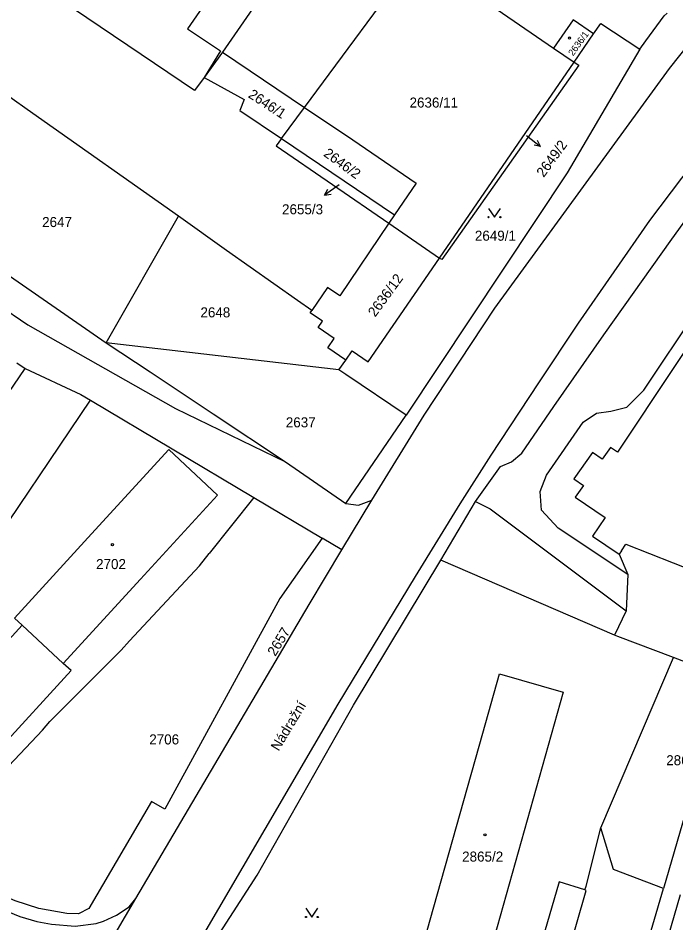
# Model space of a CAD drawing. Extents: x -527335 to -526256, y -1079142 to -1077809.
# Drawn here: x -527132.2 to -527020.7, y -1078877.1 to -1078723.7 of the extents above; entities that cross this region are included whole.
import ezdxf

# ---------------------------------------------------------------- set-up
doc = ezdxf.new("R2010")
doc.units = 0
for name, color, linetype in [('Vrstva 1', 7, 'Continuous'), ('Vrstva 2', 7, 'Continuous'), ('Vrstva 3', 7, 'Continuous'), ('Vrstva 4', 7, 'Continuous'), ('Vrstva 5', 7, 'Continuous'), ('Vrstva 7', 7, 'Continuous')]:
    doc.layers.add(name, color=color, linetype=linetype)

msp = doc.modelspace()

# ---------------------------------------------------------------- linework, layer by layer
at = {"layer": 'Vrstva 1'}
for p, q in [((-527097.53, -1078729.48), (-527100.64, -1078733.75)), ((-527097.53, -1078729.48), (-527083.63, -1078738.83)), ((-527060.76, -1078764.37), (-527037.96, -1078731.19)), ((-527087.53, -1078744.11), (-527083.63, -1078738.83)), ((-527087.53, -1078744.11), (-527068.38, -1078757.06)), ((-527117.23, -1078778.72), (-527104.99, -1078757.3)), ((-527068.38, -1078757.06), (-527069.34, -1078758.47)), ((-527148.09, -1078757.41), (-527117.23, -1078778.72)), ((-527069.34, -1078758.47), (-527060.76, -1078764.37)), ((-527077.82, -1078783.31), (-527117.23, -1078778.72)), ((-527077.82, -1078783.31), (-527076.65, -1078781.68)), ((-527076.62, -1078805.97), (-527066.43, -1078791.03)), ((-527077.3, -1078813.84), (-527072.22, -1078805.43)), ((-527077.3, -1078813.84), (-527080.64, -1078811.86)), ((-527031.1, -1078828.29), (-527060.55, -1078815.59)), ((-527131.44, -1078826.61), (-527124.5, -1078833.07)), ((-527033.44, -1078860.94), (-527021.11, -1078832.09)), ((-526983.93, -1078846.24), (-527021.11, -1078832.09))]:
    msp.add_line(p, q, dxfattribs=at)
for points in [[(-527072.22, -1078805.43), (-527063.35, -1078791.03), (-527051.39, -1078772.86), (-527021.8, -1078732.24), (-527016.31, -1078725.38), (-526999.22, -1078705.77), (-526979.26, -1078684.5), (-526961.36, -1078666.17), (-526945.34, -1078649.61), (-526932.24, -1078641.62), (-526929.63, -1078639.61), (-526929.14, -1078637.23), (-526930.46, -1078635.68), (-526927.65, -1078633), (-526895.17, -1078602.34)], [(-527100.64, -1078733.75), (-527102.25, -1078735.96), (-527127.31, -1078719.02), (-527111.05, -1078694.45)], [(-527080.84, -1078705.04), (-527083.41, -1078706.65), (-527085.52, -1078706.27), (-527089.43, -1078704.54), (-527090.21, -1078705.74), (-527091.13, -1078707.66), (-527103.45, -1078725.55), (-527097.86, -1078729.26), (-527100.64, -1078733.75)], [(-527080.84, -1078705.04), (-527085.2, -1078711.65), (-527097.53, -1078729.48)], [(-527083.63, -1078738.83), (-527064.48, -1078712.94), (-527041.46, -1078728.79), (-527037.96, -1078731.19)], [(-527026.84, -1078728.96), (-527025.8, -1078727.55), (-527022.69, -1078723.31), (-527022.2, -1078722.85)], [(-526998.63, -1078724.92), (-527007.36, -1078735.07), (-527019.76, -1078750.86), (-527025.21, -1078757.99), (-527037.26, -1078775.41), (-527043.97, -1078785.5), (-527052.05, -1078797.8), (-527057.33, -1078806.06), (-527064.89, -1078818.36), (-527077.97, -1078839.97), (-527106.45, -1078888.73), (-527179.38, -1079013.92), (-527179.74, -1079015.3)], [(-527060.55, -1078815.59), (-527054.66, -1078805.64), (-527050.43, -1078799.71), (-527048.56, -1078798.89), (-527046.8, -1078797.42), (-527041.37, -1078789.55), (-527032.93, -1078777.37), (-527021.38, -1078761.15), (-527014.2, -1078751.18), (-527004.39, -1078737.66), (-526998.1, -1078729.59), (-526996.78, -1078727.49), (-526996.17, -1078726.12), (-526997.1, -1078724.79), (-526998.63, -1078724.92)], [(-527037.96, -1078731.19), (-527034.65, -1078726.37), (-527033.45, -1078724.63), (-527026.84, -1078728.96)], [(-527026.84, -1078728.96), (-527039.13, -1078749.94), (-527066.43, -1078791.03)], [(-527037.96, -1078731.19), (-527037.19, -1078731.69), (-527060.38, -1078764.63), (-527060.76, -1078764.37)], [(-527100.64, -1078733.75), (-527093.86, -1078737.51), (-527094.58, -1078739.34), (-527087.53, -1078744.11)], [(-527104.99, -1078757.3), (-527129.66, -1078739.88), (-527134.11, -1078736.73), (-527148.09, -1078757.41)], [(-527083.63, -1078738.83), (-527075.44, -1078744.34), (-527064.73, -1078751.68), (-527068.38, -1078757.06)], [(-527087.53, -1078744.11), (-527088.44, -1078745.34), (-527069.34, -1078758.47)], [(-527082.38, -1078773.28), (-527084.82, -1078771.55), (-527096.82, -1078763.08), (-527104.99, -1078757.3)], [(-527069.34, -1078758.47), (-527077.66, -1078770.78), (-527079.76, -1078769.36), (-527082.38, -1078773.28)], [(-527076.65, -1078781.68), (-527075.57, -1078780.1), (-527072.85, -1078781.96), (-527060.76, -1078764.37)], [(-527003.07, -1078773.49), (-527011.16, -1078768.09), (-527030.63, -1078797.3), (-527031.8, -1078796.49), (-527033.21, -1078798.48), (-527034.85, -1078797.32), (-527038.02, -1078801.77), (-527036.37, -1078802.94), (-527037.76, -1078804.91), (-527032.72, -1078808.35), (-527034.82, -1078811.52), (-527030.31, -1078814.54), (-527028.85, -1078818), (-527029.14, -1078824.18), (-527031.1, -1078828.29)], [(-527076.65, -1078781.68), (-527079.71, -1078779.62), (-527078.61, -1078778.01), (-527081.31, -1078776.16), (-527080.58, -1078775.08), (-527082.65, -1078773.68), (-527082.38, -1078773.28)], [(-527117.23, -1078778.72), (-527109.79, -1078783.67), (-527099.09, -1078790.78), (-527086.87, -1078798.91), (-527076.62, -1078805.97)], [(-527132.36, -1078782.16), (-527130.96, -1078783.09), (-527121.51, -1078787.51), (-527119.86, -1078788.49)], [(-527066.43, -1078791.03), (-527076.61, -1078784.13), (-527077.82, -1078783.31)], [(-527172.24, -1078856.19), (-527141.71, -1078814.86), (-527138.98, -1078816.71), (-527119.86, -1078788.49)], [(-527119.86, -1078788.49), (-527092.2, -1078804.98), (-527080.64, -1078811.86)], [(-527124.5, -1078833.07), (-527111.43, -1078818.8), (-527098.36, -1078804.54), (-527106.61, -1078796.85), (-527119.69, -1078811.12), (-527132.76, -1078825.39), (-527131.44, -1078826.61)], [(-527076.62, -1078805.97), (-527074.47, -1078806.26), (-527072.22, -1078805.43)], [(-527080.64, -1078811.86), (-527087.81, -1078822.05), (-527107.3, -1078857.78), (-527109.58, -1078856.49), (-527120.15, -1078874.63), (-527121.91, -1078875.54), (-527123.9, -1078875.45), (-527128.65, -1078874.62), (-527132.64, -1078873.34), (-527143.8, -1078868.59), (-527146.2, -1078867.57), (-527172.24, -1078856.19)], [(-527112.22, -1078872.94), (-527082.87, -1078823.07), (-527077.3, -1078813.84)], [(-527106.29, -1078891.74), (-527106.04, -1078891.29), (-527091.65, -1078868.97), (-527075.33, -1078840.18), (-527060.55, -1078815.59)], [(-527131.44, -1078826.61), (-527144.07, -1078840.4), (-527144.58, -1078840.95), (-527157.72, -1078855.29), (-527149.33, -1078862.84), (-527144.03, -1078857.05), (-527136.25, -1078848.56), (-527135.69, -1078847.95), (-527123.17, -1078834.29), (-527124.5, -1078833.07)], [(-527021.11, -1078832.09), (-527030.54, -1078828.5), (-527031.1, -1078828.29)], [(-527221.67, -1078833.78), (-527221.62, -1078835.3), (-527221.22, -1078836.2), (-527220.43, -1078836.77), (-527209.47, -1078841.8), (-527166.12, -1078861.35), (-527149.23, -1078868.84), (-527131.87, -1078875.96), (-527128.98, -1078876.81), (-527126.47, -1078877.28), (-527122.5, -1078877.6), (-527118.95, -1078877.18), (-527117.66, -1078876.76), (-527115.47, -1078875.73), (-527113.35, -1078874.31), (-527112.22, -1078872.94)], [(-527066.43, -1078890.98), (-527061.74, -1078874.35), (-527053.44, -1078844.9), (-527050.62, -1078834.87), (-527039.79, -1078837.98), (-527052.51, -1078883.15), (-527052.59, -1078883.43), (-527052.98, -1078884.85), (-527053.07, -1078885.16), (-527055.62, -1078894.2), (-527062.72, -1078892.18)], [(-527012.78, -1078858.89), (-527018.69, -1078857.04), (-527022.83, -1078871.21)], [(-527036.12, -1078871.48), (-527035.93, -1078870.81), (-527033.44, -1078860.94)], [(-527022.83, -1078871.21), (-527031.31, -1078868.03), (-527033.44, -1078860.94)], [(-527036.12, -1078871.48), (-527040.52, -1078870.12), (-527056.07, -1078923.59), (-527056.32, -1078925.44), (-527061.28, -1078942.36), (-527061.88, -1078943.73), (-527062.74, -1078944.48), (-527063.56, -1078944.86), (-527064.35, -1078944.84), (-527109.61, -1078934.05), (-527111.47, -1078933.13)], [(-526995.85, -1078962.29), (-527010.74, -1078958.5), (-527025.58, -1078954.47), (-527044.12, -1078949.38), (-527051.99, -1078948.07), (-527054.24, -1078947.27), (-527055.63, -1078946.46), (-527056.51, -1078945.37), (-527056.83, -1078944.49), (-527056.47, -1078943.22), (-527035.9, -1078871.55), (-527036.12, -1078871.48)], [(-527019.98, -1078872.28), (-527025.47, -1078891.17), (-527018.06, -1078893.37), (-527016.26, -1078887.19), (-527005.85, -1078890.36), (-527009.3, -1078901.58), (-527026.96, -1078896.29), (-527030.11, -1078907.12), (-527028.71, -1078907.46), (-527026.81, -1078901.4), (-527012.81, -1078905.7), (-527018.48, -1078924.2), (-527019.58, -1078927.78), (-527031.54, -1078924.07), (-527033.7, -1078923.4), (-527032.59, -1078919.86), (-527029.47, -1078909.9), (-527033.77, -1078908.6), (-527022.83, -1078871.21)], [(-527131.27, -1078905.61), (-527124.93, -1078894.36), (-527124.67, -1078892.26), (-527123.81, -1078892.07), (-527117.09, -1078881.21), (-527112.22, -1078872.94)]]:
    msp.add_lwpolyline(points, dxfattribs=at)
at = {"layer": 'Vrstva 3'}
for points in [[(-527052.46, -1078755.95), (-527051.46, -1078757.45), (-527050.46, -1078755.95)], [(-527083.39, -1078874.56), (-527082.39, -1078876.06), (-527081.39, -1078874.56)]]:
    msp.add_lwpolyline(points, dxfattribs=at)
for centre in [(-527052.46, -1078757.45), (-527050.46, -1078757.45), (-527083.39, -1078876.06), (-527081.39, -1078876.06)]:
    msp.add_circle(centre, 0.1, dxfattribs=at)
at = {"layer": 'Vrstva 4'}
for p, q in [((-527206.11, -1078724.43), (-527130.49, -1078775.7)), ((-527038.14, -1078723.99), (-527041.46, -1078728.79)), ((-527034.65, -1078726.37), (-527038.14, -1078723.99)), ((-527026.13, -1078786.78), (-527013.46, -1078767.65)), ((-527130.49, -1078775.7), (-527105.49, -1078789.87)), ((-527178.67, -1078853.11), (-527130.96, -1078783.09)), ((-527029.05, -1078789.66), (-527026.13, -1078786.78)), ((-527105.49, -1078789.87), (-527086.87, -1078798.91)), ((-527036.42, -1078792.21), (-527034.18, -1078790.66)), ((-527034.18, -1078790.66), (-527031.73, -1078790.3)), ((-527031.73, -1078790.3), (-527029.05, -1078789.66)), ((-527042.65, -1078801.19), (-527036.42, -1078792.21)), ((-527043.72, -1078803.96), (-527042.65, -1078801.19)), ((-527043.51, -1078807.08), (-527043.72, -1078803.96)), ((-527092.2, -1078804.98), (-527099.77, -1078814.45)), ((-527054.66, -1078805.64), (-527052.21, -1078806.89)), ((-527052.21, -1078806.89), (-527029.14, -1078824.18)), ((-527040.69, -1078810.14), (-527043.51, -1078807.08)), ((-527028.85, -1078818), (-527040.69, -1078810.14)), ((-527029.95, -1078814), (-527030.31, -1078814.54)), ((-527029.95, -1078814), (-527029.19, -1078812.84)), ((-527029.19, -1078812.84), (-527005.06, -1078822.46)), ((-527101.43, -1078816.55), (-527099.77, -1078814.45)), ((-527113.27, -1078829.25), (-527101.43, -1078816.55)), ((-527114.7, -1078830.81), (-527113.27, -1078829.25)), ((-527126.76, -1078842.91), (-527114.7, -1078830.81)), ((-527128.03, -1078844.4), (-527126.76, -1078842.91)), ((-527137.41, -1078854.29), (-527128.03, -1078844.4))]:
    msp.add_line(p, q, dxfattribs=at)
at = {"layer": 'Vrstva 5'}
for centre in [(-527038.74, -1078727.08), (-527116.18, -1078812.95), (-527053.06, -1078862.12)]:
    msp.add_circle(centre, 0.175, dxfattribs=at)
at = {"layer": 'Vrstva 7'}
for p, q in [((-527046.02, -1078743.59), (-527043.66, -1078745.44)), ((-527043.66, -1078745.44), (-527044.14, -1078744.43)), ((-527043.66, -1078745.44), (-527044.75, -1078745.22)), ((-527077.76, -1078751.97), (-527080.22, -1078753.69)), ((-527080.22, -1078753.69), (-527079.69, -1078752.71)), ((-527080.22, -1078753.69), (-527079.11, -1078753.53))]:
    msp.add_line(p, q, dxfattribs=at)

# ---------------------------------------------------------------- texts
at = {"layer": 'Vrstva 2'}
for s, height, rotation, p in [('2636/1', 1.139, 54, (-527038.14, -1078730.22)), ('2646/1', 1.7, 327, (-527093.3, -1078737.05)), ('2649/2', 1.7, 54, (-527043.11, -1078750.81)), ('2646/2', 1.7, 324, (-527080.54, -1078746.97)), ('2636/12', 1.7, 54, (-527071.66, -1078774.48)), ('2657', 1.7, 59, (-527088.58, -1078831.99))]:
    msp.add_text(s, height=height, rotation=rotation, dxfattribs=at).set_placement(p)
for s, p in [('2636/11', (-527065.84, -1078738.87)), ('2655/3', (-527087.44, -1078756.96)), ('2647', (-527128.08, -1078759.12)), ('2649/1', (-527054.77, -1078761.44)), ('2648', (-527101.26, -1078774.43)), ('2637', (-527086.8, -1078793.07)), ('2702', (-527118.94, -1078817.09)), ('2706', (-527109.93, -1078846.81)), ('2868/1', (-527022.36, -1078850.34)), ('2865/2', (-527056.93, -1078866.67))]:
    msp.add_text(s, height=1.7, dxfattribs=at).set_placement(p)
at = {"layer": 'Vrstva 7'}
msp.add_text('Nádražní', height=1.7, rotation=59, dxfattribs=at).set_placement((-527088.02, -1078848.05))

doc.saveas('drawing.dxf')
